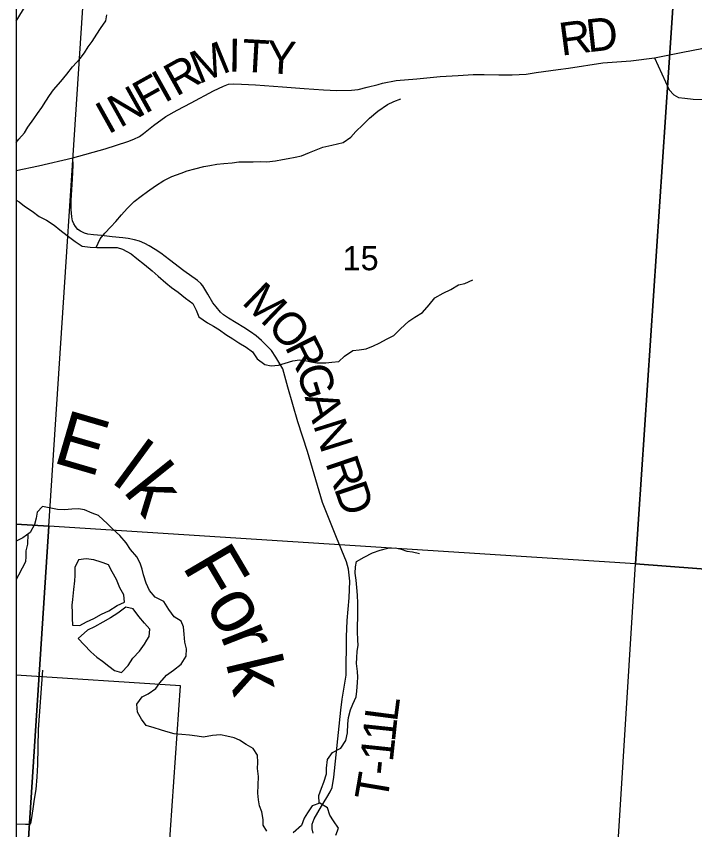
# Model space of a CAD drawing. Extents: x 0 to 34, y 0 to 22.
# Drawn here: x 2.1 to 3.275, y 15.589 to 16.998 of the extents above; entities that cross this region are included whole.
import ezdxf

# ---------------------------------------------------------------- set-up
doc = ezdxf.new("R2010")
doc.units = 0
for name, color, linetype in [('Default', 7, 'Continuous'), ('GM_X_City_Street', 7, 'Continuous'), ('GM_X_Minor_Lake', 7, 'Continuous'), ('GM_X_Minor_River', 7, 'Continuous'), ('GM_X_Minor_River_Text', 7, 'Continuous'), ('GM_X_Rail_Line', 7, 'Continuous'), ('GM_X_Section', 7, 'Continuous'), ('GM_X_Section_Text', 7, 'Continuous'), ('GM_X_Township_Road', 7, 'Continuous'), ('GM_X_Township_Road_Text', 7, 'Continuous'), ('SC_Scratch1', 7, 'Continuous'), ('SH_Data', 7, 'Continuous')]:
    doc.layers.add(name, color=color, linetype=linetype)

msp = doc.modelspace()

# ---------------------------------------------------------------- linework, layer by layer
at = {"layer": 'Default'}
for points in [[(2.1, 17.1522), (2.1, 16.1183), (2.1564, 16.1145), (2.2239, 17.1453)], [(2.1, 16.1183), (2.1, 15.2462), (2.1564, 16.1145)], [(2.1, 15.2462), (2.1, 15.0784), (3.1079, 15.0113), (3.1721, 16.0496), (2.1564, 16.1145)], [(2.1, 15.8568), (2.1, 14.5567), (2.3019, 14.5422), (2.3116, 14.694), (2.3586, 15.464), (2.3842, 15.838)]]:
    msp.add_lwpolyline(points, close=True, dxfattribs=at)
at = {"layer": 'GM_X_City_Street'}
msp.add_lwpolyline([(2.1, 15.5993), (2.1003, 15.5992), (2.1158, 15.5987), (2.1225, 15.5988), (2.1253, 15.6), (2.1261, 15.6059), (2.129, 15.6251), (2.1316, 15.6417), (2.1344, 15.6589), (2.1359, 15.6807), (2.1371, 15.7016), (2.1387, 15.7628), (2.1461, 15.8655)], dxfattribs=at)
at = {"layer": 'GM_X_Minor_Lake'}
for points in [[(2.2506, 16.0512), (2.247, 16.0525), (2.2341, 16.0563), (2.2212, 16.0582), (2.2076, 16.0562), (2.2012, 16.0433), (2.2013, 16.0293), (2.2009, 16.0198), (2.1991, 16.005), (2.1972, 15.9876), (2.1965, 15.9777), (2.1969, 15.9648), (2.1966, 15.9553), (2.1974, 15.9432)], [(2.1974, 15.9432), (2.2099, 15.9425), (2.2216, 15.9489), (2.2344, 15.955), (2.2477, 15.9623), (2.2605, 15.9684), (2.2749, 15.9771), (2.2877, 15.9829), (2.2862, 15.9961), (2.2793, 16.0079), (2.2736, 16.0223), (2.2663, 16.0355), (2.2599, 16.0476), (2.2506, 16.0512)], [(2.3263, 15.9174), (2.3299, 15.9234), (2.331, 15.9363), (2.3223, 15.9465), (2.312, 15.9586), (2.3025, 15.9715), (2.29, 15.9745), (2.276, 15.9642), (2.2632, 15.9559), (2.25, 15.9483), (2.2352, 15.9403), (2.2231, 15.9345), (2.2069, 15.9201)], [(2.2069, 15.9201), (2.2175, 15.9095), (2.2293, 15.8974), (2.2396, 15.8876), (2.2491, 15.8811), (2.2604, 15.8724), (2.2703, 15.8649), (2.2824, 15.8615), (2.2937, 15.8737), (2.3017, 15.8862), (2.3133, 15.8984), (2.322, 15.9105), (2.3263, 15.9174)]]:
    msp.add_lwpolyline(points, dxfattribs=at)
at = {"layer": 'GM_X_Minor_River'}
for points in [[(2.1, 16.7791), (2.1045, 16.7848), (2.114, 16.7958), (2.12, 16.8057), (2.1302, 16.8201), (2.137, 16.8296), (2.1441, 16.8399), (2.1513, 16.8509), (2.1573, 16.8604), (2.1645, 16.8703), (2.1773, 16.8851), (2.1875, 16.8976), (2.1976, 16.9105), (2.2108, 16.9246), (2.218, 16.9345), (2.2244, 16.9447), (2.2316, 16.9542), (2.2395, 16.9671), (2.2459, 16.9766), (2.2549, 16.9899), (2.2568, 17.0006)], [(2.2384, 16.5975), (2.2455, 16.6122), (2.2535, 16.6221), (2.264, 16.6331), (2.2723, 16.6426), (2.2821, 16.654), (2.2919, 16.6647), (2.3044, 16.6768), (2.3161, 16.686), (2.3274, 16.6943), (2.341, 16.7042), (2.3554, 16.7137), (2.3694, 16.7202), (2.3856, 16.7263), (2.3958, 16.7301), (2.4091, 16.7336), (2.4249, 16.7374), (2.4352, 16.7393), (2.4473, 16.7416), (2.4594, 16.7428), (2.4741, 16.744), (2.4855, 16.7455), (2.4999, 16.7459), (2.5101, 16.746), (2.5222, 16.7464), (2.5339, 16.7457), (2.5491, 16.7472), (2.5608, 16.7495), (2.5706, 16.7514), (2.5831, 16.7541), (2.5937, 16.7564), (2.6077, 16.7621), (2.6194, 16.7667), (2.6311, 16.7709), (2.6466, 16.7747), (2.6565, 16.7767), (2.6663, 16.7793), (2.6792, 16.7885), (2.6878, 16.798), (2.6999, 16.8101), (2.7116, 16.8212), (2.7259, 16.8333), (2.7426, 16.8448), (2.7539, 16.8505), (2.766, 16.8551)], [(2.1, 16.6792), (2.1049, 16.6763), (2.1144, 16.6692), (2.1277, 16.6605), (2.1398, 16.651), (2.1523, 16.645), (2.1656, 16.6359), (2.1755, 16.628), (2.1884, 16.6182), (2.202, 16.6076), (2.2142, 16.5996), (2.2282, 16.5982), (2.2395, 16.5974), (2.2524, 16.5971), (2.2641, 16.5975), (2.2747, 16.5975), (2.2842, 16.5945), (2.299, 16.5862), (2.3085, 16.5783), (2.3218, 16.5677), (2.3351, 16.5567), (2.3457, 16.548), (2.359, 16.5359), (2.3688, 16.528), (2.3802, 16.52), (2.3931, 16.5098), (2.406, 16.5004), (2.4117, 16.489), (2.4163, 16.4773), (2.4311, 16.4671), (2.4417, 16.461), (2.452, 16.455), (2.463, 16.4467), (2.4751, 16.4391), (2.4854, 16.4323), (2.4979, 16.4248), (2.5089, 16.4164), (2.5173, 16.4043), (2.5305, 16.3945), (2.5415, 16.3926), (2.554, 16.3938), (2.5657, 16.3969), (2.579, 16.4011), (2.5907, 16.403), (2.6005, 16.4019), (2.61, 16.3996), (2.6202, 16.3974), (2.6358, 16.3974), (2.6467, 16.3986), (2.6585, 16.4001), (2.6686, 16.4093), (2.6826, 16.4188), (2.694, 16.4199), (2.7057, 16.4219), (2.7186, 16.4268), (2.7284, 16.4318), (2.7424, 16.439), (2.7537, 16.4451), (2.7654, 16.4565), (2.7797, 16.4698), (2.7899, 16.477), (2.8032, 16.4847), (2.8152, 16.4983), (2.8247, 16.5101), (2.839, 16.5185), (2.8526, 16.5246), (2.8658, 16.5326), (2.8768, 16.5349), (2.8904, 16.5414)], [(2.5339, 15.5868), (2.5278, 15.5967), (2.5278, 15.6065), (2.5251, 15.6202), (2.5213, 15.6304), (2.5194, 15.6406), (2.5182, 15.6524), (2.5189, 15.6664), (2.5192, 15.6812), (2.518, 15.6948), (2.5184, 15.7055), (2.5176, 15.7184), (2.51, 15.7297), (2.4982, 15.7369), (2.4868, 15.7444), (2.4774, 15.7482), (2.4645, 15.7512), (2.4535, 15.7531), (2.4399, 15.7523), (2.424, 15.7496), (2.4134, 15.7511), (2.4001, 15.753), (2.3865, 15.7541), (2.3732, 15.7552), (2.3592, 15.7593), (2.3498, 15.7619), (2.3388, 15.7653), (2.3251, 15.7698), (2.3171, 15.7804), (2.3099, 15.7925), (2.3087, 15.8062), (2.3181, 15.8191), (2.3284, 15.8241), (2.3419, 15.8336), (2.3487, 15.8435), (2.3604, 15.8568), (2.3725, 15.8655), (2.3853, 15.8758), (2.3944, 15.8894), (2.3947, 15.9023), (2.392, 15.9141), (2.3905, 15.9277), (2.3893, 15.9403), (2.3855, 15.9505), (2.3733, 15.958), (2.3642, 15.9705), (2.3558, 15.9845), (2.3407, 15.9917), (2.3308, 16.0034), (2.3247, 16.0163), (2.3205, 16.0307), (2.3182, 16.0402), (2.3147, 16.0508), (2.3087, 16.0618), (2.298, 16.0746), (2.2904, 16.086), (2.2794, 16.0985), (2.2672, 16.1098), (2.2577, 16.1189), (2.2426, 16.1333), (2.2316, 16.1371), (2.2179, 16.1431), (2.2077, 16.145), (2.1963, 16.1442), (2.1838, 16.143), (2.1714, 16.1437), (2.157, 16.1467), (2.1456, 16.149), (2.1362, 16.1391), (2.1343, 16.1285), (2.1313, 16.1175), (2.1238, 16.1038), (2.1113, 16.0943), (2.1011, 16.0893), (2.1, 16.0889)], [(2.12, 16.1009), (2.1193, 16.0833), (2.1167, 16.0723), (2.1164, 16.0624), (2.116, 16.053), (2.11, 16.0423), (2.104, 16.0298), (2.1, 16.0223)], [(2.6248, 15.635), (2.6238, 15.6481), (2.6283, 15.661), (2.6324, 15.6712), (2.6373, 15.6857), (2.6373, 15.6955), (2.6387, 15.7107), (2.6474, 15.7225), (2.6618, 15.7305), (2.6708, 15.7438), (2.6738, 15.757), (2.6741, 15.7722), (2.6752, 15.7836), (2.679, 15.7969), (2.6827, 15.8067), (2.6884, 15.8193), (2.6895, 15.8291), (2.6909, 15.8439), (2.6913, 15.8534), (2.6909, 15.8633), (2.6893, 15.8769), (2.6897, 15.8868), (2.6904, 15.8985), (2.6919, 15.908), (2.6914, 15.9179), (2.691, 15.9315), (2.691, 15.9429), (2.6917, 15.9558), (2.6913, 15.9683), (2.6912, 15.9812), (2.6908, 15.9952), (2.6896, 16.0085), (2.6888, 16.021), (2.6869, 16.0331), (2.6873, 16.0441), (2.6891, 16.0536), (2.7023, 16.0608), (2.7167, 16.0685), (2.7303, 16.073), (2.7435, 16.0765), (2.7564, 16.0773), (2.7663, 16.0747), (2.7761, 16.0716), (2.786, 16.0705), (2.7985, 16.0675)], [(2.6536, 15.5795), (2.6581, 15.592), (2.6493, 15.6042), (2.6432, 15.614), (2.639, 15.6269), (2.6254, 15.6352), (2.6125, 15.6306), (2.6046, 15.6185), (2.5986, 15.609), (2.5937, 15.5961), (2.5797, 15.5839)]]:
    msp.add_lwpolyline(points, dxfattribs=at)
at = {"layer": 'GM_X_Rail_Line'}
msp.add_lwpolyline([(2.1, 16.9893), (2.1704, 17.1051), (2.2013, 17.1731), (2.2243, 17.2382), (2.2428, 17.3133), (2.3248, 17.6437), (2.3306, 17.7087), (2.3319, 17.774), (2.3234, 17.8446), (2.3066, 17.9007), (2.2655, 18.002), (2.1, 18.4495)], dxfattribs=at)
at = {"layer": 'GM_X_Section'}
for points in [[(3.2396, 17.0555), (3.1721, 16.0496), (2.1564, 16.1145), (2.2239, 17.1453)], [(3.2396, 17.0555), (4.2561, 17.0047), (4.189, 15.9719), (3.1721, 16.0496)], [(4.189, 15.9719), (4.1172, 14.9476), (3.1079, 15.0113), (3.1721, 16.0496)]]:
    msp.add_lwpolyline(points, close=True, dxfattribs=at)
at = {"layer": 'GM_X_Township_Road'}
for points in [[(2.7265, 16.8799), (2.7344, 16.8819), (2.7581, 16.8864), (2.7935, 16.8897), (2.8339, 16.8933), (2.8651, 16.8954), (2.8913, 16.8972), (2.9105, 16.8969), (2.9358, 16.8962), (2.959, 16.8965), (2.983, 16.8976), (3.0005, 16.9004), (3.0382, 16.9054), (3.0564, 16.9081), (3.1157, 16.917), (3.1641, 16.9207), (3.2052, 16.9261), (3.2541, 16.9355), (3.2872, 16.9419), (3.3196, 16.9521), (3.3698, 16.9715), (3.4181, 16.9893), (3.4427, 16.9984)], [(3.2052, 16.9261), (3.2304, 16.8707), (3.2385, 16.862), (3.247, 16.8574), (3.2576, 16.8558), (3.2719, 16.8545), (3.2897, 16.8539)], [(2.1, 16.7307), (2.1383, 16.7386), (2.1977, 16.7528), (2.254, 16.7683), (2.2934, 16.7807), (2.3035, 16.785), (2.3135, 16.7897), (2.3203, 16.7948), (2.3374, 16.8086), (2.3588, 16.824), (2.3787, 16.8352), (2.4031, 16.8481), (2.4417, 16.8687), (2.4587, 16.8766), (2.4678, 16.8801), (2.4756, 16.881), (2.4898, 16.8803), (2.5141, 16.8792), (2.5611, 16.8755), (2.5983, 16.873), (2.6323, 16.8707), (2.6549, 16.8694), (2.6806, 16.8696), (2.6922, 16.8712), (2.7078, 16.8751), (2.7265, 16.8799)], [(2.614, 15.5828), (2.6126, 15.5908), (2.6124, 15.5989), (2.6157, 15.608), (2.6283, 15.6301), (2.6378, 15.645), (2.6436, 15.6544), (2.6473, 15.6622), (2.65, 15.6799), (2.6622, 15.7963), (2.6642, 15.8151), (2.6712, 15.8569), (2.6721, 15.9232), (2.6728, 15.9515), (2.6765, 15.9906), (2.6778, 16.0196), (2.6756, 16.0401), (2.6717, 16.0532), (2.6546, 16.0954), (2.6303, 16.1557), (2.6042, 16.2439), (2.5875, 16.2954), (2.57, 16.3556), (2.5614, 16.3874), (2.5492, 16.4073), (2.5418, 16.4188), (2.5334, 16.4277), (2.5246, 16.4364), (2.5152, 16.4444), (2.5057, 16.4514), (2.4939, 16.459), (2.4808, 16.4669), (2.4676, 16.4749), (2.4589, 16.4807), (2.4536, 16.4854), (2.4459, 16.4945), (2.4402, 16.5017), (2.4315, 16.5165), (2.4231, 16.5307), (2.4194, 16.535), (2.414, 16.5402), (2.3901, 16.5569), (2.3652, 16.5758), (2.3506, 16.5874), (2.3403, 16.5941), (2.3304, 16.6003), (2.3226, 16.6045), (2.3133, 16.6084), (2.3047, 16.6108), (2.2939, 16.6129), (2.2845, 16.6143), (2.2661, 16.616), (2.2474, 16.618), (2.2336, 16.6193), (2.2237, 16.6203), (2.2179, 16.6222), (2.2113, 16.6255), (2.2068, 16.6288), (2.2027, 16.6337), (2.1998, 16.6382), (2.1975, 16.6436), (2.1963, 16.6502), (2.195, 16.6632), (2.195, 16.6792), (2.1972, 16.7155), (2.1985, 16.7402), (2.1977, 16.7528)]]:
    msp.add_lwpolyline(points, dxfattribs=at)
at = {"layer": 'SC_Scratch1'}
msp.add_lwpolyline([(2.1, 19.1982), (2.1, 14.1), (5.0535, 14.1), (5.0814, 14.5016), (5.1049, 14.8414), (5.1794, 15.9156), (5.2761, 17.2534), (5.2869, 17.4026), (5.3506, 18.2846), (5.3662, 18.4999), (5.4007, 18.9779), (5.182, 18.9932), (4.7997, 19.0196), (4.7394, 19.0241), (4.3628, 19.0495), (3.3448, 19.1146), (2.3572, 19.1804)], close=True, dxfattribs=at)
at = {"layer": 'SH_Data'}
msp.add_line((2.1, 20.9), (2.1, 14.1), dxfattribs=at)

# ---------------------------------------------------------------- texts
at = {"layer": 'GM_X_Minor_River_Text'}
for s, height, rotation, p in [('E', 0.0947, 343.7189, (2.1606, 16.2258)), ('l', 0.0947, 323.7178, (2.2628, 16.1912)), ('k', 0.0947, 308.7181, (2.2836, 16.1751)), ('Fo', 0.09471, 300.5019, (2.3862, 16.0456)), ('r', 0.0947, 291.5028, (2.4525, 15.9264)), ('k', 0.0947, 283.5038, (2.4623, 15.879))]:
    msp.add_text(s, height=height, rotation=rotation, dxfattribs=at).set_placement(p)
at = {"layer": 'GM_X_Section_Text'}
msp.add_text('15', height=0.04186, rotation=0, dxfattribs=at).set_placement((2.6652, 16.558))
at = {"layer": 'GM_X_Township_Road_Text'}
for s, rotation, p in [('R', 7.4876, (3.0439, 16.9294)), ('D', 6.3772, (3.0899, 16.9354)), ('M', 22.2111, (2.416, 16.88)), ('I', 359.1725, (2.4672, 16.9022)), ('T', 356.8356, (2.4899, 16.9019)), ('Y', 356.6686, (2.5323, 16.8996)), ('R', 29.0618, (2.3769, 16.8581)), ('F', 29.1626, (2.323, 16.8281)), ('I', 29.1703, (2.3565, 16.8468)), ('N', 29.1654, (2.2794, 16.8037)), ('I', 29.163, (2.259, 16.7924)), ('M', 315.9983, (2.4889, 16.5012)), ('O', 312.8616, (2.5326, 16.459)), ('R', 296.6035, (2.5642, 16.4258)), ('G', 287.3786, (2.5842, 16.3863)), ('A', 286.8451, (2.5991, 16.3387)), ('N', 287.5069, (2.6138, 16.2902)), ('R', 288.8039, (2.6348, 16.2246)), ('D', 288.9065, (2.6499, 16.1803)), ('L', 82.5911, (2.7593, 15.7745)), ('1', 83.9207, (2.7557, 15.74)), ('1', 83.995, (2.752, 15.7052)), ('-', 83.946, (2.7495, 15.682)), ('T', 80.3939, (2.7419, 15.6363))]:
    msp.add_text(s, height=0.0568, rotation=rotation, dxfattribs=at).set_placement(p)

doc.saveas('drawing.dxf')
